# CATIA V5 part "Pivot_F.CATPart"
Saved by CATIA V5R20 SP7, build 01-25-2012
Part number: Pivot_F
Bounding box of the stored display mesh (mm): x 147.5 to 152.5, y 27.5 to 32.5, z -6 to 6
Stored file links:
  D:\IFMA\COURS\2A\projet balance IAO\catia\Pivot_F.CATPart
  D:\IFMA\COURS\2A\projet balance IAO\catia\Ass_projet_balance.CATProduct
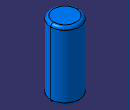
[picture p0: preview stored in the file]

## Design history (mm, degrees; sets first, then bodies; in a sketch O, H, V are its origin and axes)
Set1
  Plane1 "Plan_plateau_droit": linked copy from another document
  Point1 "Point.F": linked copy from another document
Body1 (main body)
  Sketch1 on Plane1, origin (0, 0, 0), H (1, 0, 0), V (0, 1, 0)
    circle A1 centre (150, 30) radius 2.5
    point P1 (150, 30)
    reference projected point E1 (150, 30) from Point1
    radius A1 = 2.5
    coincidence: P1 E1
  Pad1: profile Sketch1, direction (0, 0, 1), length 6, mirrored extent
  Fillet1: radius 0.5, on edge [face of Pad1 from Sketch1.A1 | end face of Pad1]; edge [start face of Pad1 | face of Pad1 from Sketch1.A1]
